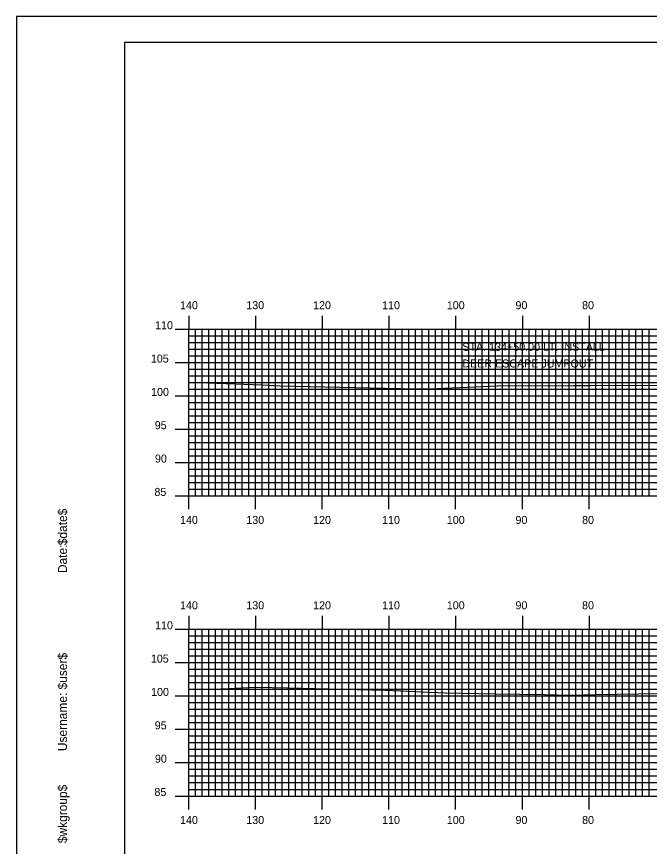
# Model space of a CAD drawing. Extents: x 1774777 to 1775120, y 442591 to 442811.
# Drawn here: x 1774776.9 to 1774871.7, y 442686.1 to 442810.5 of the extents above; entities that cross this region are included whole.
import ezdxf

# ---------------------------------------------------------------- set-up
doc = ezdxf.new("R2010")
doc.units = 0
for name, color, linetype in [('BORDER', 7, 'Continuous'), ('D_Text_Standard', 7, 'Continuous'), ('H_V ANNOTATION', 7, 'Continuous'), ('MAJOR', 7, 'Continuous'), ('MINOR', 7, 'Continuous'), ('PLOT BOUNDARY', 7, 'Continuous'), ('S_Roadway_Centerline', 7, 'Continuous')]:
    doc.layers.add(name, color=color, linetype=linetype)

msp = doc.modelspace()

# ---------------------------------------------------------------- linework, layer by layer
at = {"layer": 'BORDER'}
msp.add_lwpolyline([(1774793.09, 442596.67), (1775113.09, 442596.67), (1775113.09, 442806.67), (1774793.09, 442806.67)], close=True, dxfattribs=at)
at = {"layer": 'MAJOR'}
for p, q in [((1774802.69, 442765.67), (1774802.69, 442763.67)), ((1774812.69, 442765.67), (1774812.69, 442763.67)), ((1774822.69, 442765.67), (1774822.69, 442763.67)), ((1774832.69, 442765.67), (1774832.69, 442763.67)), ((1774842.69, 442765.67), (1774842.69, 442763.67)), ((1774852.69, 442765.67), (1774852.69, 442763.67)), ((1774862.69, 442765.67), (1774862.69, 442763.67)), ((1774800.68, 442763.67), (1774802.69, 442763.67)), ((1774802.69, 442763.67), (1775082.69, 442763.67)), ((1774802.69, 442738.67), (1774802.69, 442763.67)), ((1774802.69, 442738.67), (1774802.69, 442763.67)), ((1774802.69, 442763.67), (1775082.69, 442763.67)), ((1774812.69, 442738.67), (1774812.69, 442763.67)), ((1774822.69, 442738.67), (1774822.69, 442763.67)), ((1774832.69, 442738.67), (1774832.69, 442763.67)), ((1774842.69, 442738.67), (1774842.69, 442763.67)), ((1774852.69, 442738.67), (1774852.69, 442763.67)), ((1774862.69, 442738.67), (1774862.69, 442763.67)), ((1774800.68, 442758.67), (1774802.69, 442758.67)), ((1774802.69, 442758.67), (1775082.69, 442758.67)), ((1774800.68, 442753.67), (1774802.69, 442753.67)), ((1774802.69, 442753.67), (1775082.69, 442753.67)), ((1774800.68, 442748.67), (1774802.69, 442748.67)), ((1774802.69, 442748.67), (1775082.69, 442748.67)), ((1774800.68, 442743.67), (1774802.69, 442743.67)), ((1774802.69, 442743.67), (1775082.69, 442743.67)), ((1774800.68, 442738.67), (1774802.69, 442738.67)), ((1774802.69, 442738.67), (1775082.69, 442738.67)), ((1774802.69, 442738.67), (1775082.69, 442738.67)), ((1774802.69, 442736.66), (1774802.69, 442738.67)), ((1774812.69, 442736.66), (1774812.69, 442738.67)), ((1774822.69, 442736.66), (1774822.69, 442738.67)), ((1774832.69, 442736.66), (1774832.69, 442738.67)), ((1774842.69, 442736.66), (1774842.69, 442738.67)), ((1774852.69, 442736.66), (1774852.69, 442738.67)), ((1774862.69, 442736.66), (1774862.69, 442738.67)), ((1774802.69, 442720.67), (1774802.69, 442718.67)), ((1774812.69, 442720.67), (1774812.69, 442718.67)), ((1774822.69, 442720.67), (1774822.69, 442718.67)), ((1774832.69, 442720.67), (1774832.69, 442718.67)), ((1774842.69, 442720.67), (1774842.69, 442718.67)), ((1774852.69, 442720.67), (1774852.69, 442718.67)), ((1774862.69, 442720.67), (1774862.69, 442718.67)), ((1774800.68, 442718.67), (1774802.69, 442718.67)), ((1774802.69, 442718.67), (1775082.69, 442718.67)), ((1774802.69, 442693.67), (1774802.69, 442718.67)), ((1774802.69, 442693.67), (1774802.69, 442718.67)), ((1774802.69, 442718.67), (1775082.69, 442718.67)), ((1774812.69, 442693.67), (1774812.69, 442718.67)), ((1774822.69, 442693.67), (1774822.69, 442718.67)), ((1774832.69, 442693.67), (1774832.69, 442718.67)), ((1774842.69, 442693.67), (1774842.69, 442718.67)), ((1774852.69, 442693.67), (1774852.69, 442718.67)), ((1774862.69, 442693.67), (1774862.69, 442718.67)), ((1774800.68, 442713.67), (1774802.69, 442713.67)), ((1774802.69, 442713.67), (1775082.69, 442713.67)), ((1774800.68, 442708.67), (1774802.69, 442708.67)), ((1774802.69, 442708.67), (1775082.69, 442708.67)), ((1774800.68, 442703.67), (1774802.69, 442703.67)), ((1774802.69, 442703.67), (1775082.69, 442703.67)), ((1774800.68, 442698.67), (1774802.69, 442698.67)), ((1774802.69, 442698.67), (1775082.69, 442698.67)), ((1774800.68, 442693.67), (1774802.69, 442693.67)), ((1774802.69, 442693.67), (1775082.69, 442693.67)), ((1774802.69, 442693.67), (1775082.69, 442693.67)), ((1774802.69, 442691.66), (1774802.69, 442693.67)), ((1774812.69, 442691.66), (1774812.69, 442693.67)), ((1774822.69, 442691.66), (1774822.69, 442693.67)), ((1774832.69, 442691.66), (1774832.69, 442693.67)), ((1774842.69, 442691.66), (1774842.69, 442693.67)), ((1774852.69, 442691.66), (1774852.69, 442693.67)), ((1774862.69, 442691.66), (1774862.69, 442693.67))]:
    msp.add_line(p, q, dxfattribs=at)
at = {"layer": 'MINOR'}
for p, q in [((1774802.69, 442762.67), (1775082.69, 442762.67)), ((1774802.69, 442762.67), (1774804.69, 442762.67)), ((1774803.69, 442738.67), (1774803.69, 442763.67)), ((1774804.69, 442738.67), (1774804.69, 442763.67)), ((1774805.69, 442738.67), (1774805.69, 442763.67)), ((1774806.69, 442738.67), (1774806.69, 442763.67)), ((1774807.69, 442738.67), (1774807.69, 442763.67)), ((1774808.69, 442738.67), (1774808.69, 442763.67)), ((1774809.69, 442738.67), (1774809.69, 442763.67)), ((1774810.69, 442738.67), (1774810.69, 442763.67)), ((1774811.69, 442738.67), (1774811.69, 442763.67)), ((1774813.69, 442738.67), (1774813.69, 442763.67)), ((1774814.69, 442738.67), (1774814.69, 442763.67)), ((1774815.69, 442738.67), (1774815.69, 442763.67)), ((1774816.69, 442738.67), (1774816.69, 442763.67)), ((1774817.69, 442738.67), (1774817.69, 442763.67)), ((1774818.69, 442738.67), (1774818.69, 442763.67)), ((1774819.69, 442738.67), (1774819.69, 442763.67)), ((1774820.69, 442738.67), (1774820.69, 442763.67)), ((1774821.69, 442738.67), (1774821.69, 442763.67)), ((1774823.69, 442738.67), (1774823.69, 442763.67)), ((1774824.69, 442738.67), (1774824.69, 442763.67)), ((1774825.69, 442738.67), (1774825.69, 442763.67)), ((1774826.69, 442738.67), (1774826.69, 442763.67)), ((1774827.69, 442738.67), (1774827.69, 442763.67)), ((1774828.69, 442738.67), (1774828.69, 442763.67)), ((1774829.69, 442738.67), (1774829.69, 442763.67)), ((1774830.69, 442738.67), (1774830.69, 442763.67)), ((1774831.69, 442738.67), (1774831.69, 442763.67)), ((1774833.69, 442738.67), (1774833.69, 442763.67)), ((1774834.69, 442738.67), (1774834.69, 442763.67)), ((1774835.69, 442738.67), (1774835.69, 442763.67)), ((1774836.69, 442738.67), (1774836.69, 442763.67)), ((1774837.69, 442738.67), (1774837.69, 442763.67)), ((1774838.69, 442738.67), (1774838.69, 442763.67)), ((1774839.69, 442738.67), (1774839.69, 442763.67)), ((1774840.69, 442738.67), (1774840.69, 442763.67)), ((1774841.69, 442738.67), (1774841.69, 442763.67)), ((1774843.69, 442738.67), (1774843.69, 442763.67)), ((1774844.69, 442738.67), (1774844.69, 442763.67)), ((1774845.69, 442738.67), (1774845.69, 442763.67)), ((1774846.69, 442738.67), (1774846.69, 442763.67)), ((1774847.69, 442738.67), (1774847.69, 442763.67)), ((1774848.69, 442738.67), (1774848.69, 442763.67)), ((1774849.69, 442738.67), (1774849.69, 442763.67)), ((1774850.69, 442738.67), (1774850.69, 442763.67)), ((1774851.69, 442738.67), (1774851.69, 442763.67)), ((1774853.69, 442738.67), (1774853.69, 442763.67)), ((1774854.69, 442738.67), (1774854.69, 442763.67)), ((1774855.69, 442738.67), (1774855.69, 442763.67)), ((1774856.69, 442738.67), (1774856.69, 442763.67)), ((1774857.69, 442738.67), (1774857.69, 442763.67)), ((1774858.69, 442738.67), (1774858.69, 442763.67)), ((1774859.69, 442738.67), (1774859.69, 442763.67)), ((1774860.69, 442738.67), (1774860.69, 442763.67)), ((1774861.69, 442738.67), (1774861.69, 442763.67)), ((1774863.69, 442738.67), (1774863.69, 442763.67)), ((1774864.69, 442738.67), (1774864.69, 442763.67)), ((1774865.69, 442738.67), (1774865.69, 442763.67)), ((1774866.69, 442738.67), (1774866.69, 442763.67)), ((1774867.69, 442738.67), (1774867.69, 442763.67)), ((1774868.69, 442738.67), (1774868.69, 442763.67)), ((1774869.69, 442738.67), (1774869.69, 442763.67)), ((1774870.69, 442738.67), (1774870.69, 442763.67)), ((1774871.69, 442738.67), (1774871.69, 442763.67)), ((1774802.69, 442761.67), (1775082.69, 442761.67)), ((1774802.69, 442761.67), (1774804.69, 442761.67)), ((1774802.69, 442760.67), (1775082.69, 442760.67)), ((1774802.69, 442760.67), (1774804.69, 442760.67)), ((1774802.69, 442759.67), (1775082.69, 442759.67)), ((1774802.69, 442759.67), (1774804.69, 442759.67)), ((1774802.69, 442757.67), (1775082.69, 442757.67)), ((1774802.69, 442757.67), (1774804.69, 442757.67)), ((1774802.69, 442756.67), (1775082.69, 442756.67)), ((1774802.69, 442756.67), (1774804.69, 442756.67)), ((1774802.69, 442755.67), (1775082.69, 442755.67)), ((1774802.69, 442755.67), (1774804.69, 442755.67)), ((1774802.69, 442754.67), (1775082.69, 442754.67)), ((1774802.69, 442754.67), (1774804.69, 442754.67)), ((1774802.69, 442752.67), (1775082.69, 442752.67)), ((1774802.69, 442752.67), (1774804.69, 442752.67)), ((1774802.69, 442751.67), (1775082.69, 442751.67)), ((1774802.69, 442751.67), (1774804.69, 442751.67)), ((1774802.69, 442750.67), (1775082.69, 442750.67)), ((1774802.69, 442750.67), (1774804.69, 442750.67)), ((1774802.69, 442749.67), (1775082.69, 442749.67)), ((1774802.69, 442749.67), (1774804.69, 442749.67)), ((1774802.69, 442747.67), (1775082.69, 442747.67)), ((1774802.69, 442747.67), (1774804.69, 442747.67)), ((1774802.69, 442746.67), (1775082.69, 442746.67)), ((1774802.69, 442746.67), (1774804.69, 442746.67)), ((1774802.69, 442745.67), (1775082.69, 442745.67)), ((1774802.69, 442745.67), (1774804.69, 442745.67)), ((1774802.69, 442744.67), (1775082.69, 442744.67)), ((1774802.69, 442744.67), (1774804.69, 442744.67)), ((1774802.69, 442742.67), (1775082.69, 442742.67)), ((1774802.69, 442742.67), (1774804.69, 442742.67)), ((1774802.69, 442741.67), (1775082.69, 442741.67)), ((1774802.69, 442741.67), (1774804.69, 442741.67)), ((1774802.69, 442740.67), (1775082.69, 442740.67)), ((1774802.69, 442740.67), (1774804.69, 442740.67)), ((1774802.69, 442739.67), (1775082.69, 442739.67)), ((1774802.69, 442739.67), (1774804.69, 442739.67)), ((1774803.69, 442693.67), (1774803.69, 442718.67)), ((1774804.69, 442693.67), (1774804.69, 442718.67)), ((1774805.69, 442693.67), (1774805.69, 442718.67)), ((1774806.69, 442693.67), (1774806.69, 442718.67)), ((1774807.69, 442693.67), (1774807.69, 442718.67)), ((1774808.69, 442693.67), (1774808.69, 442718.67)), ((1774809.69, 442693.67), (1774809.69, 442718.67)), ((1774810.69, 442693.67), (1774810.69, 442718.67)), ((1774811.69, 442693.67), (1774811.69, 442718.67)), ((1774813.69, 442693.67), (1774813.69, 442718.67)), ((1774814.69, 442693.67), (1774814.69, 442718.67)), ((1774815.69, 442693.67), (1774815.69, 442718.67)), ((1774816.69, 442693.67), (1774816.69, 442718.67)), ((1774817.69, 442693.67), (1774817.69, 442718.67)), ((1774818.69, 442693.67), (1774818.69, 442718.67)), ((1774819.69, 442693.67), (1774819.69, 442718.67)), ((1774820.69, 442693.67), (1774820.69, 442718.67)), ((1774821.69, 442693.67), (1774821.69, 442718.67)), ((1774823.69, 442693.67), (1774823.69, 442718.67)), ((1774824.69, 442693.67), (1774824.69, 442718.67)), ((1774825.69, 442693.67), (1774825.69, 442718.67)), ((1774826.69, 442693.67), (1774826.69, 442718.67)), ((1774827.69, 442693.67), (1774827.69, 442718.67)), ((1774828.69, 442693.67), (1774828.69, 442718.67)), ((1774829.69, 442693.67), (1774829.69, 442718.67)), ((1774830.69, 442693.67), (1774830.69, 442718.67)), ((1774831.69, 442693.67), (1774831.69, 442718.67)), ((1774833.69, 442693.67), (1774833.69, 442718.67)), ((1774834.69, 442693.67), (1774834.69, 442718.67)), ((1774835.69, 442693.67), (1774835.69, 442718.67)), ((1774836.69, 442693.67), (1774836.69, 442718.67)), ((1774837.69, 442693.67), (1774837.69, 442718.67)), ((1774838.69, 442693.67), (1774838.69, 442718.67)), ((1774839.69, 442693.67), (1774839.69, 442718.67)), ((1774840.69, 442693.67), (1774840.69, 442718.67)), ((1774841.69, 442693.67), (1774841.69, 442718.67)), ((1774843.69, 442693.67), (1774843.69, 442718.67)), ((1774844.69, 442693.67), (1774844.69, 442718.67)), ((1774845.69, 442693.67), (1774845.69, 442718.67)), ((1774846.69, 442693.67), (1774846.69, 442718.67)), ((1774847.69, 442693.67), (1774847.69, 442718.67)), ((1774848.69, 442693.67), (1774848.69, 442718.67)), ((1774849.69, 442693.67), (1774849.69, 442718.67)), ((1774850.69, 442693.67), (1774850.69, 442718.67)), ((1774851.69, 442693.67), (1774851.69, 442718.67)), ((1774853.69, 442693.67), (1774853.69, 442718.67)), ((1774854.69, 442693.67), (1774854.69, 442718.67)), ((1774855.69, 442693.67), (1774855.69, 442718.67)), ((1774856.69, 442693.67), (1774856.69, 442718.67)), ((1774857.69, 442693.67), (1774857.69, 442718.67)), ((1774858.69, 442693.67), (1774858.69, 442718.67)), ((1774859.69, 442693.67), (1774859.69, 442718.67)), ((1774860.69, 442693.67), (1774860.69, 442718.67)), ((1774861.69, 442693.67), (1774861.69, 442718.67)), ((1774863.69, 442693.67), (1774863.69, 442718.67)), ((1774864.69, 442693.67), (1774864.69, 442718.67)), ((1774865.69, 442693.67), (1774865.69, 442718.67)), ((1774866.69, 442693.67), (1774866.69, 442718.67)), ((1774867.69, 442693.67), (1774867.69, 442718.67)), ((1774868.69, 442693.67), (1774868.69, 442718.67)), ((1774869.69, 442693.67), (1774869.69, 442718.67)), ((1774870.69, 442693.67), (1774870.69, 442718.67)), ((1774871.69, 442693.67), (1774871.69, 442718.67)), ((1774802.69, 442717.67), (1775082.69, 442717.67)), ((1774802.69, 442717.67), (1774804.69, 442717.67)), ((1774802.69, 442716.67), (1775082.69, 442716.67)), ((1774802.69, 442716.67), (1774804.69, 442716.67)), ((1774802.69, 442715.67), (1775082.69, 442715.67)), ((1774802.69, 442715.67), (1774804.69, 442715.67)), ((1774802.69, 442714.67), (1775082.69, 442714.67)), ((1774802.69, 442714.67), (1774804.69, 442714.67)), ((1774802.69, 442712.67), (1775082.69, 442712.67)), ((1774802.69, 442712.67), (1774804.69, 442712.67)), ((1774802.69, 442711.67), (1775082.69, 442711.67)), ((1774802.69, 442711.67), (1774804.69, 442711.67)), ((1774802.69, 442710.67), (1775082.69, 442710.67)), ((1774802.69, 442710.67), (1774804.69, 442710.67)), ((1774802.69, 442709.67), (1775082.69, 442709.67)), ((1774802.69, 442709.67), (1774804.69, 442709.67)), ((1774802.69, 442707.67), (1775082.69, 442707.67)), ((1774802.69, 442707.67), (1774804.69, 442707.67)), ((1774802.69, 442706.67), (1775082.69, 442706.67)), ((1774802.69, 442706.67), (1774804.69, 442706.67)), ((1774802.69, 442705.67), (1775082.69, 442705.67)), ((1774802.69, 442705.67), (1774804.69, 442705.67)), ((1774802.69, 442704.67), (1775082.69, 442704.67)), ((1774802.69, 442704.67), (1774804.69, 442704.67)), ((1774802.69, 442702.67), (1775082.69, 442702.67)), ((1774802.69, 442702.67), (1774804.69, 442702.67)), ((1774802.69, 442701.67), (1775082.69, 442701.67)), ((1774802.69, 442701.67), (1774804.69, 442701.67)), ((1774802.69, 442700.67), (1775082.69, 442700.67)), ((1774802.69, 442700.67), (1774804.69, 442700.67)), ((1774802.69, 442699.67), (1775082.69, 442699.67)), ((1774802.69, 442699.67), (1774804.69, 442699.67)), ((1774802.69, 442697.67), (1775082.69, 442697.67)), ((1774802.69, 442697.67), (1774804.69, 442697.67)), ((1774802.69, 442696.67), (1775082.69, 442696.67)), ((1774802.69, 442696.67), (1774804.69, 442696.67)), ((1774802.69, 442695.67), (1775082.69, 442695.67)), ((1774802.69, 442695.67), (1774804.69, 442695.67)), ((1774802.69, 442694.67), (1775082.69, 442694.67)), ((1774802.69, 442694.67), (1774804.69, 442694.67))]:
    msp.add_line(p, q, dxfattribs=at)
at = {"layer": 'PLOT BOUNDARY'}
msp.add_lwpolyline([(1774776.9, 442590.55), (1775116.9, 442590.55), (1775116.9, 442810.55), (1774776.9, 442810.55)], close=True, dxfattribs=at)
at = {"layer": 'S_Roadway_Centerline'}
for points in [[(1774802.69, 442755.71), (1774802.82, 442755.72), (1774813.68, 442755.33), (1774816.36, 442755.19), (1774836.62, 442754.73), (1774837.78, 442754.73), (1774838.79, 442754.75), (1774848.95, 442755.16), (1774860.38, 442755.25), (1774860.42, 442755.25), (1774860.46, 442755.25), (1774862.9, 442755.25), (1774883.51, 442755.27)], [(1774802.69, 442709.7), (1774803.89, 442709.7), (1774807.49, 442709.73), (1774812.92, 442709.98), (1774817.48, 442709.87), (1774832.16, 442709.52), (1774841.11, 442709.12), (1774848.62, 442708.98), (1774856.02, 442708.87), (1774859.97, 442708.8), (1774863.7, 442708.87), (1774879.58, 442709.13)]]:
    msp.add_lwpolyline(points, dxfattribs=at)

# ---------------------------------------------------------------- texts
at = {"layer": 'BORDER'}
for s, p in [('$date$', (1774784.45, 442731.28)), ('Date:', (1774784.45, 442727.1)), ('$user$', (1774784.45, 442709.65)), ('Username:', (1774784.45, 442700.4)), ('$wkgroup$', (1774784.45, 442686.6))]:
    msp.add_text(s, height=1.339, rotation=90, dxfattribs=at).set_placement(p)
at = {"layer": 'D_Text_Standard'}
for s, p in [('STA. 134+50.00 LT. INSTALL ', (1774843.69, 442760.43)), ('DEER ESCAPE JUMPOUT', (1774843.69, 442757.93))]:
    msp.add_text(s, height=1.2, dxfattribs=at).set_placement(p)
at = {"layer": 'H_V ANNOTATION'}
for s, p in [('140', (1774801.39, 442766.67)), ('130', (1774811.32, 442766.67)), ('120', (1774821.33, 442766.67)), ('110', (1774831.67, 442766.67)), ('100', (1774841.37, 442766.67)), ('90', (1774851.66, 442766.67)), ('80', (1774861.64, 442766.67)), ('110', (1774797.65, 442763.67)), ('105', (1774797.02, 442758.67)), ('100', (1774797.05, 442753.67)), ('95', (1774797.6, 442748.67)), ('90', (1774797.63, 442743.67)), ('85', (1774797.55, 442738.67)), ('140', (1774801.39, 442734.47)), ('130', (1774811.32, 442734.47)), ('120', (1774821.33, 442734.47)), ('110', (1774831.67, 442734.47)), ('100', (1774841.37, 442734.47)), ('90', (1774851.66, 442734.47)), ('80', (1774861.64, 442734.47)), ('140', (1774801.39, 442721.67)), ('130', (1774811.32, 442721.67)), ('120', (1774821.33, 442721.67)), ('110', (1774831.67, 442721.67)), ('100', (1774841.37, 442721.67)), ('90', (1774851.66, 442721.67)), ('80', (1774861.64, 442721.67)), ('110', (1774797.65, 442718.67)), ('105', (1774797.02, 442713.67)), ('100', (1774797.05, 442708.67)), ('95', (1774797.6, 442703.67)), ('90', (1774797.63, 442698.67)), ('85', (1774797.55, 442693.67)), ('140', (1774801.39, 442689.47)), ('130', (1774811.32, 442689.47)), ('120', (1774821.33, 442689.47)), ('110', (1774831.67, 442689.47)), ('100', (1774841.37, 442689.47)), ('90', (1774851.66, 442689.47)), ('80', (1774861.64, 442689.47))]:
    msp.add_text(s, height=1.2, dxfattribs=at).set_placement(p)
at = {"layer": 'MAJOR'}
for p in [(1774802.68, 442738.67), (1774802.68, 442693.67)]:
    msp.add_text('-', height=0.012, dxfattribs=at).set_placement(p)

doc.saveas('drawing.dxf')
